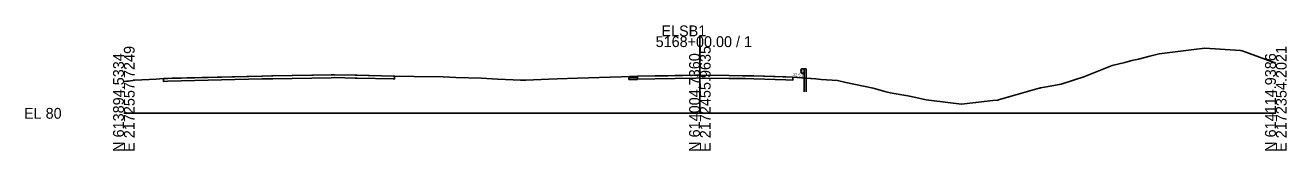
# Model space of a CAD drawing. Extents: x -26 to 1303, y -3010 to 12023.
# Drawn here: x -25.7 to 302.8, y -2009.7 to -1977.2 of the extents above; entities that cross this region are included whole.
import ezdxf

# ---------------------------------------------------------------- set-up
doc = ezdxf.new("R2010")
doc.units = 0
for name, color, linetype in [('RD_GPK_XS_Cell', 7, 'Continuous'), ('RD_PD_Final_TrvlWay', 7, 'Continuous'), ('RD_XS_Base', 7, 'Continuous'), ('RD_XS_ExGround', 7, 'Continuous'), ('RD_XS_ExPaveRet', 7, 'Continuous'), ('RD_XS_GR', 7, 'Continuous'), ('RD_XS_Pave', 7, 'Continuous'), ('RD_XS_PaveOvlay_CP', 7, 'Continuous'), ('RD_XS_TieSlope', 7, 'Continuous'), ('RD_XS_TX_ShdSlope', 7, 'Continuous')]:
    doc.layers.add(name, color=color, linetype=linetype)

msp = doc.modelspace()

# ---------------------------------------------------------------- linework, layer by layer
at = {"layer": 'RD_GPK_XS_Cell'}
for p, q in [((150, -2000), (150, -1980)), ((0, -2000), (150, -2000)), ((150, -2000), (300, -2000))]:
    msp.add_line(p, q, dxfattribs=at)
at = {"layer": 'RD_PD_Final_TrvlWay'}
for p, q in [((177.17, -1994.44), (177.17, -1990.83)), ((177.17, -1990.83), (177.67, -1990.87)), ((177.67, -1990.87), (177.67, -1994.44))]:
    msp.add_line(p, q, dxfattribs=at)
at = {"layer": 'RD_XS_Base'}
for p, q in [((131.49, -1990.76), (131.99, -1990.74)), ((131.49, -1991.26), (131.49, -1990.76)), ((131.49, -1990.79), (131.49, -1990.79)), ((131.99, -1990.74), (133.72, -1990.69)), ((131.99, -1990.74), (131.99, -1990.74)), ((131.98, -1991.24), (131.49, -1991.26)), ((133.72, -1991.19), (131.99, -1991.24)), ((133.72, -1991.13), (133.72, -1991.19))]:
    msp.add_line(p, q, dxfattribs=at)
at = {"layer": 'RD_XS_ExGround'}
msp.add_lwpolyline([(0, -1991.77), (0.79, -1991.67), (1.17, -1991.63), (2.84, -1991.43), (8.44, -1991.09), (10.3, -1990.97), (12.58, -1990.91), (36.11, -1990.33), (38.46, -1990.28), (54.77, -1989.98), (60.2, -1990.11), (70.49, -1990.34), (75.62, -1990.42), (83.12, -1990.56), (86.44, -1990.68), (93.17, -1990.88), (97.26, -1991.09), (101.41, -1991.32), (103.25, -1991.38), (104.68, -1991.37), (110.66, -1991.11), (112.8, -1991.02), (118.15, -1990.84), (129.51, -1990.5), (133.72, -1990.38), (141.74, -1990.23), (149.51, -1990.08), (157.52, -1990.18), (161.56, -1990.24), (164.05, -1990.31), (174.23, -1990.6), (180.19, -1991.07), (181.61, -1991.18), (185.86, -1991.52), (187.98, -1991.99), (195.13, -1993.5), (198.2, -1994.35), (199.56, -1994.66), (204.17, -1995.48), (206.21, -1995.89), (208.97, -1996.5), (215.31, -1997.31), (218.1, -1997.66), (221.12, -1997.3), (226.31, -1996.69), (227.57, -1996.54), (227.74, -1996.5), (231.06, -1995.53), (238.37, -1993.5), (238.51, -1993.45), (238.72, -1993.39), (239.71, -1993.23), (244.09, -1992.45), (247.33, -1991.41), (250, -1990.5), (254.3, -1988.77), (257.34, -1987.57), (260.68, -1986.82), (262.48, -1986.3), (264.27, -1985.91), (267.2, -1985.14), (269.61, -1984.55), (278.63, -1983.45), (281.48, -1983.11), (290.75, -1983.73), (291.23, -1983.76), (293.1, -1984.46), (300, -1987)], dxfattribs=at)
at = {"layer": 'RD_XS_ExPaveRet'}
for p, q in [((70.49, -1990.34), (70.35, -1990.33)), ((161.77, -1990.24), (161.56, -1990.24)), ((164.05, -1990.31), (161.77, -1990.24)), ((172.39, -1990.54), (164.05, -1990.31)), ((174.23, -1990.6), (172.39, -1990.54))]:
    msp.add_line(p, q, dxfattribs=at)
for points in [[(60.75, -1990.12), (60.22, -1990.11), (54.79, -1989.98), (54.77, -1989.98), (54.77, -1989.98), (54.73, -1989.98), (54.02, -1990), (38.76, -1990.28), (38.55, -1990.28), (36.11, -1990.33), (35.96, -1990.33), (11.48, -1990.94), (10.3, -1990.97), (10.3, -1990.97), (10.3, -1990.97), (10.3, -1990.97), (10.3, -1990.97), (10.3, -1991.68), (10.3, -1991.72), (10.3, -1991.72), (10.3, -1991.72), (10.3, -1991.72), (10.3, -1991.72), (11.48, -1991.69), (35.96, -1991.08), (36.11, -1991.08), (38.55, -1991.03), (38.76, -1991.03), (54.02, -1990.75), (54.73, -1990.74), (54.77, -1990.73), (54.77, -1990.73), (54.79, -1990.73), (60.22, -1990.86), (60.75, -1990.87), (70.25, -1991.08), (70.49, -1991.09), (70.49, -1991.05), (70.49, -1990.34), (70.25, -1990.33), (60.75, -1990.12)], [(54.73, -1989.98), (54.02, -1990), (38.76, -1990.28), (38.46, -1990.28), (36.11, -1990.33), (35.96, -1990.33), (12.58, -1990.91), (11.48, -1990.94), (10.3, -1990.97), (10.3, -1990.97), (10.3, -1990.97)], [(10.3, -1990.97), (10.3, -1991.68), (10.3, -1991.72), (10.3, -1991.72), (10.3, -1991.72), (11.48, -1991.69), (35.96, -1991.08), (36.11, -1991.08), (38.55, -1991.03), (38.76, -1991.03), (54.02, -1990.75), (54.73, -1990.74), (54.77, -1990.73), (54.77, -1990.73), (54.79, -1990.73), (60.22, -1990.86), (60.75, -1990.87), (70.25, -1991.08), (70.49, -1991.09), (70.49, -1991.05), (70.49, -1990.34)], [(54.77, -1989.98), (54.77, -1989.98), (54.73, -1989.98)], [(60.47, -1990.12), (60.22, -1990.11), (60.2, -1990.11), (54.79, -1989.98), (54.77, -1989.98)], [(70.35, -1990.33), (70.25, -1990.33), (60.75, -1990.12), (60.47, -1990.12)], [(174.23, -1990.6), (172.39, -1990.54), (164.05, -1990.31), (161.77, -1990.24), (161.56, -1990.24), (161.22, -1990.23), (157.52, -1990.18), (150, -1990.09), (149.85, -1990.09), (149.51, -1990.08), (149.48, -1990.08), (148.95, -1990.09), (138.25, -1990.29), (133.72, -1990.38), (133.72, -1990.38), (133.72, -1990.89), (133.72, -1991.13), (133.72, -1991.13), (138.25, -1991.04), (148.95, -1990.84), (149.48, -1990.83), (149.51, -1990.83), (149.85, -1990.84), (150, -1990.84), (157.52, -1990.93), (161.22, -1990.98), (161.56, -1990.99), (161.77, -1990.99), (164.05, -1991.06), (172.39, -1991.29), (174.23, -1991.35), (174.23, -1991.35), (174.23, -1991.11), (174.23, -1990.6), (174.23, -1990.6)], [(148.77, -1990.1), (138.25, -1990.29), (133.72, -1990.38), (133.72, -1990.89), (133.72, -1991.13), (138.25, -1991.04), (148.95, -1990.84), (149.48, -1990.83), (149.51, -1990.83), (149.85, -1990.84), (150, -1990.84), (157.52, -1990.93), (161.22, -1990.98), (161.56, -1990.99), (161.77, -1990.99), (164.05, -1991.06), (172.39, -1991.29), (174.23, -1991.35), (174.23, -1991.35), (174.23, -1991.11), (174.23, -1990.6)], [(157.52, -1990.18), (150, -1990.09), (149.85, -1990.09), (149.51, -1990.08), (149.51, -1990.08), (149.48, -1990.08), (148.95, -1990.09), (148.77, -1990.1)], [(161.56, -1990.24), (161.22, -1990.23), (157.52, -1990.18)]]:
    msp.add_lwpolyline(points, dxfattribs=at)
at = {"layer": 'RD_XS_GR'}
for p, q in [((176.23, -1988.73), (176.43, -1988.51)), ((176.3, -1988.81), (176.23, -1988.73)), ((176.23, -1989.31), (176.43, -1989.1)), ((176.3, -1989.39), (176.23, -1989.31)), ((176.5, -1989.02), (176.3, -1988.81)), ((176.5, -1989.6), (176.3, -1989.39)), ((176.43, -1988.51), (176.5, -1988.44)), ((176.43, -1989.1), (176.5, -1989.02)), ((176.5, -1988.44), (176.5, -1989.6)), ((177.17, -1988.44), (176.5, -1988.44)), ((176.5, -1988.44), (176.5, -1988.74)), ((176.5, -1988.74), (176.5, -1989.6)), ((176.5, -1989.6), (177.17, -1989.6)), ((177.17, -1988.44), (177.17, -1990.83)), ((177.42, -1988.44), (177.17, -1988.44)), ((177.17, -1989.6), (177.17, -1988.44)), ((177.17, -1990.83), (177.67, -1990.87)), ((177.67, -1988.44), (177.42, -1988.44)), ((177.67, -1990.87), (177.67, -1988.44))]:
    msp.add_line(p, q, dxfattribs=at)
at = {"layer": 'RD_XS_Pave'}
for p, q in [((133.73, -1990.38), (131.99, -1990.43)), ((131.99, -1990.43), (131.99, -1990.43)), ((131.99, -1990.43), (131.99, -1990.59)), ((133.72, -1990.54), (131.99, -1990.59)), ((131.99, -1990.59), (133.72, -1990.54)), ((131.99, -1990.59), (131.99, -1990.59)), ((131.99, -1990.59), (131.99, -1990.74)), ((131.99, -1990.59), (131.99, -1990.59)), ((131.99, -1990.59), (131.99, -1990.59)), ((131.99, -1990.74), (133.72, -1990.69)), ((131.99, -1990.74), (131.99, -1990.74)), ((131.99, -1990.74), (131.99, -1990.74))]:
    msp.add_line(p, q, dxfattribs=at)
at = {"layer": 'RD_XS_PaveOvlay_CP'}
for p in [(133.73, -1990.38), (131.99, -1990.43)]:
    msp.add_line(p, (131.99, -1990.43), dxfattribs=at)
at = {"layer": 'RD_XS_TieSlope'}
msp.add_line((174.23, -1990.6), (179.98, -1991.06), dxfattribs=at)

# ---------------------------------------------------------------- texts
at = {"layer": 'RD_GPK_XS_Cell'}
for s, p in [('ELSB1', (140, -1980)), ('5168+00.00 / 1', (138.48, -1982.8)), ('EL 80', (-26, -2001.4))]:
    msp.add_text(s, height=2.8, dxfattribs=at).set_placement(p)
for s, p in [('E 2172557.7249', (2.8, -2010)), ('E 2172455.9635', (152.8, -2010)), ('E 2172354.2021', (302.8, -2010)), ('N 613894.5334', (0, -2010)), ('N 614004.7360', (150, -2010)), ('N 614114.9386', (300, -2010))]:
    msp.add_text(s, height=2.8, rotation=90, dxfattribs=at).set_placement(p)
at = {"layer": 'RD_XS_TX_ShdSlope'}
msp.add_text('12.5:1', height=0.75, rotation=355.4261, dxfattribs=at).set_placement((174.2, -1990.31))

doc.saveas('drawing.dxf')
